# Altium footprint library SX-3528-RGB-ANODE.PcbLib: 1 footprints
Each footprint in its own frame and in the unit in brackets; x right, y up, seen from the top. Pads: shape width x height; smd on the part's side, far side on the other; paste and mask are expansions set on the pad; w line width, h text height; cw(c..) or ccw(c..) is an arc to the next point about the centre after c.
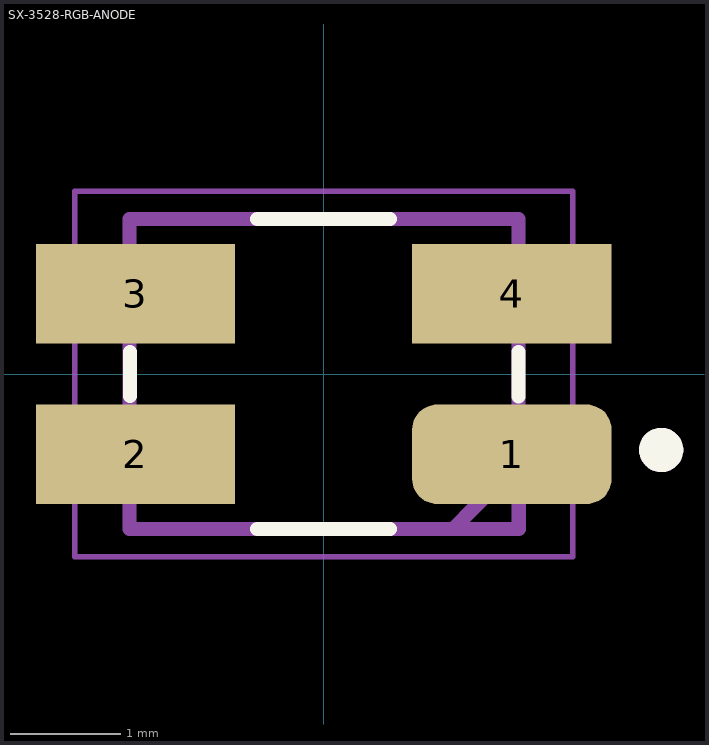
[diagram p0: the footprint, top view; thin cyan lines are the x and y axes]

## SX-3528-RGB-ANODE [mm]
pads (4):
  rrect50% 1.8x0.9 smd: 1(1.7,-0.725)
  rect 1.8x0.9 smd: 2(-1.7,-0.725) 3(-1.7,0.725) 4(1.7,0.725)
Top Overlay:
  circle w0.2: c3.048,-0.686 r0.1
  lines w0.127: -1.75,-0.2 -1.75,0.2 ; -0.6,-1.4 0.6,-1.4 ; -0.6,1.4 0.6,1.4 ; 1.761,-0.203 1.761,0.197
Mechanical 13:
  circle w0.2: c3.048,-0.686 r0.1
  lines w0.127: 1.762,-0.96 1.762,-1.4 1.17,-1.4 ; 1.17,-1.4 -1.753,-1.4 -1.753,1.4 1.758,1.4 1.758,-0.798 1.17,-1.4
Mechanical 15:
  lines w0.05: -2.25,-1.65 -2.25,1.65 2.25,1.65 2.25,-1.65 -2.25,-1.65
3D body "SX-3528-RGB-ANODE.STEP": height 0.8, standoff -1.3, extent -1.75,-1.324 1.75,1.476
